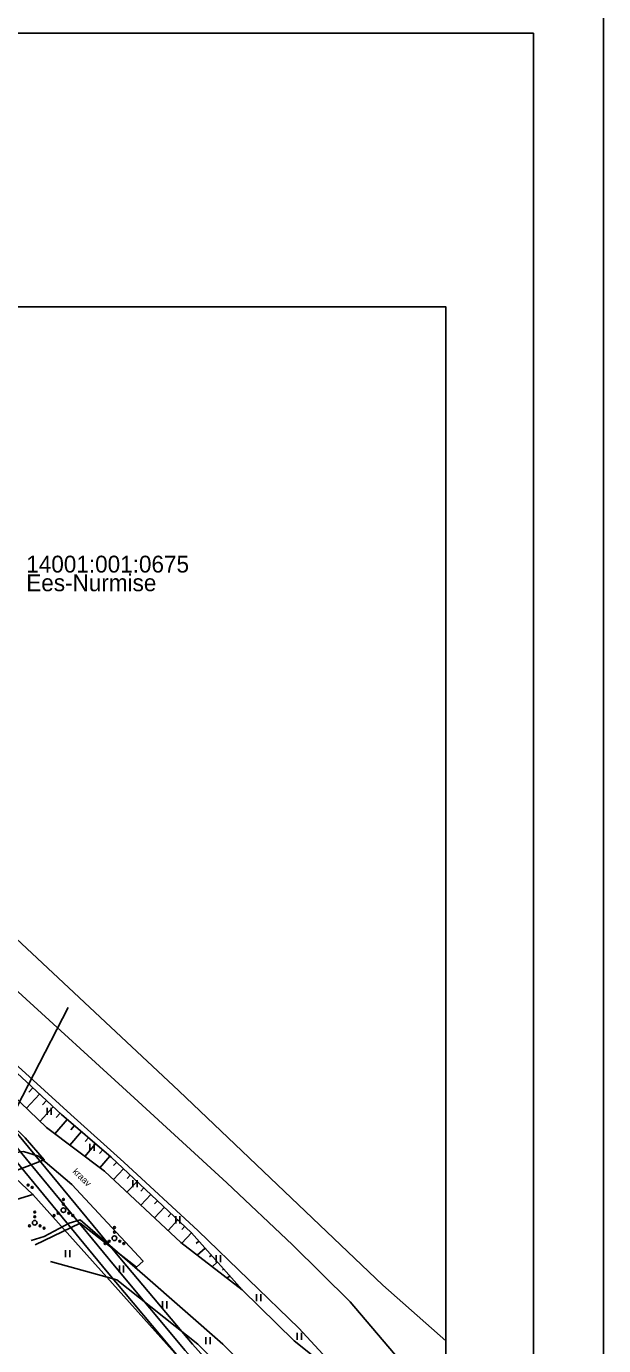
# Model space of a CAD drawing. Extents: x 567864 to 568657, y 6579839 to 6580994.
# Drawn here: x 568587.3 to 568649.1, y 6580268.5 to 6580409.7 of the extents above; entities that cross this region are included whole.
import ezdxf

# ---------------------------------------------------------------- set-up
doc = ezdxf.new("R2010")
doc.units = 0
for name, color, linetype in [('HALJASTUS', 7, 'Continuous'), ('KASUTUSALA', 7, 'Continuous'), ('KPOHULIIN', 7, 'Continuous'), ('PIIR', 7, 'Continuous'), ('PR_SIDE', 7, 'Continuous'), ('RELJEEF', 7, 'Continuous'), ('TEE', 7, 'Continuous'), ('VEEKOGU', 7, 'Continuous'), ('VORMISTUS_4', 7, 'Continuous')]:
    doc.layers.add(name, color=color, linetype=linetype)

msp = doc.modelspace()

# ---------------------------------------------------------------- linework, layer by layer
at = {"layer": 'HALJASTUS'}
for p, q in [((568589.55, 6580293.97), (568589.55, 6580293.21)), ((568590, 6580293.97), (568590, 6580293.21)), ((568594.14, 6580290.1), (568594.14, 6580289.34)), ((568594.59, 6580290.1), (568594.59, 6580289.34)), ((568598.72, 6580286.23), (568598.72, 6580285.47)), ((568599.18, 6580286.23), (568599.18, 6580285.47)), ((568603.31, 6580282.36), (568603.31, 6580281.6)), ((568603.76, 6580282.36), (568603.76, 6580281.6)), ((568591.53, 6580278.73), (568591.53, 6580277.97)), ((568591.99, 6580278.73), (568591.99, 6580277.97)), ((568597.29, 6580277.09), (568597.29, 6580276.33)), ((568597.74, 6580277.09), (568597.74, 6580276.33)), ((568607.63, 6580278.2), (568607.63, 6580277.44)), ((568608.09, 6580278.2), (568608.09, 6580277.44)), ((568601.9, 6580273.26), (568601.9, 6580272.5)), ((568602.36, 6580273.26), (568602.36, 6580272.5)), ((568611.95, 6580274.04), (568611.95, 6580273.28)), ((568612.41, 6580274.04), (568612.41, 6580273.28)), ((568606.52, 6580269.43), (568606.52, 6580268.67)), ((568606.98, 6580269.43), (568606.98, 6580268.67)), ((568616.28, 6580269.89), (568616.28, 6580269.13)), ((568616.74, 6580269.89), (568616.74, 6580269.13))]:
    msp.add_line(p, q, dxfattribs=at)
for points in [[(568588.28, 6580279.3), (568593.1, 6580281.62), (568599.12, 6580276.92), (568599.82, 6580277.57), (568592.22, 6580285.76), (568588.63, 6580288.77), (568587.02, 6580289.28), (568579.99, 6580288.26)], [(568589.92, 6580277.51), (568597.02, 6580275.57), (568605.68, 6580268.67), (568616.86, 6580257.59), (568622.86, 6580249.28), (568628.01, 6580238.44), (568630.13, 6580229.68)]]:
    msp.add_lwpolyline(points, dxfattribs=at)
for centre, radius in [((568587.53, 6580285.7), 0.1), ((568587.97, 6580285.45), 0.1), ((568591.3, 6580284.16), 0.1), ((568588.23, 6580282.81), 0.1), ((568590.74, 6580282.69), 0.1), ((568591.3, 6580283.01), 0.25), ((568591.3, 6580283.66), 0.1), ((568591.87, 6580282.69), 0.1), ((568587.67, 6580281.34), 0.1), ((568588.23, 6580281.66), 0.25), ((568588.23, 6580282.31), 0.1), ((568588.8, 6580281.34), 0.1), ((568590.3, 6580282.44), 0.1), ((568592.3, 6580282.44), 0.1), ((568596.76, 6580281.16), 0.1), ((568589.23, 6580281.09), 0.1), ((568596.76, 6580280.01), 0.25), ((568596.76, 6580280.66), 0.1), ((568595.76, 6580279.43), 0.1), ((568596.2, 6580279.68), 0.1), ((568597.33, 6580279.68), 0.1), ((568597.76, 6580279.43), 0.1)]:
    msp.add_circle(centre, radius, dxfattribs=at)
at = {"layer": 'KASUTUSALA'}
for points in [[(568461.42, 6580407.34), (568494.57, 6580376.2), (568521.29, 6580351.66), (568532.86, 6580340.57), (568578.04, 6580298.89), (568583.69, 6580294.14), (568584.34, 6580293.58), (568584.51, 6580293.44), (568597.53, 6580277.69), (568605.09, 6580268.66), (568620.33, 6580251.61)], [(568603.57, 6580267.35), (568595.99, 6580276.41), (568583.33, 6580291.74), (568581.46, 6580290.83), (568579.89, 6580292.29), (568581.72, 6580293.18), (568576.71, 6580297.39), (568531.49, 6580339.11), (568519.92, 6580350.2), (568493.21, 6580374.74), (568460.06, 6580405.87)]]:
    msp.add_lwpolyline(points, dxfattribs=at)
at = {"layer": 'KPOHULIIN'}
msp.add_lwpolyline([(568591.82, 6580304.68), (568584.43, 6580290.42), (568575.69, 6580287.52)], dxfattribs=at)
at = {"layer": 'PIIR'}
for points in [[(568513.99, 6580379.67), (568517.27, 6580376.68), (568603.64, 6580295.78), (568625.46, 6580274.99), (568632.18, 6580269.03)], [(568632.18, 6580269.03), (568625.46, 6580274.99), (568603.64, 6580295.78), (568517.27, 6580376.68), (568513.99, 6580379.67)], [(568628.53, 6580222.17), (568629.55, 6580235.74), (568618.77, 6580250.35), (568588.05, 6580284.69), (568583.66, 6580288.78), (568508.43, 6580358.86)], [(568508.43, 6580358.86), (568583.66, 6580288.78), (568588.05, 6580284.69), (568508.43, 6580260.29)], [(568508.43, 6580260.29), (568588.05, 6580284.69), (568618.77, 6580250.35), (568629.55, 6580235.74), (568628.53, 6580222.17)]]:
    msp.add_lwpolyline(points, dxfattribs=at)
at = {"layer": 'PR_SIDE'}
msp.add_lwpolyline([(568418.48, 6580444.49), (568438.25, 6580426.85), (568460.74, 6580406.61), (568493.89, 6580375.47), (568520.61, 6580350.93), (568532.18, 6580339.84), (568577.38, 6580298.14), (568583.8, 6580292.74), (568596.76, 6580277.05), (568604.33, 6580268.01), (568619.55, 6580250.98), (568628.57, 6580238.42), (568627.43, 6580222.17)], dxfattribs=at)
at = {"layer": 'RELJEEF'}
for p, q in [((568588.76, 6580295.42), (568587.36, 6580293.91)), ((568588.03, 6580296.1), (568587.61, 6580295.65)), ((568590.22, 6580294.05), (568588.8, 6580292.52)), ((568589.49, 6580294.73), (568589.07, 6580294.28)), ((568591.71, 6580292.71), (568590.39, 6580291.18)), ((568590.95, 6580293.37), (568590.53, 6580292.91)), ((568593.22, 6580291.41), (568591.99, 6580289.97)), ((568592.47, 6580292.06), (568592.08, 6580291.62)), ((568594.74, 6580290.11), (568593.59, 6580288.76)), ((568593.98, 6580290.76), (568593.62, 6580290.34)), ((568595.5, 6580289.45), (568595.16, 6580289.06)), ((568596.26, 6580288.8), (568595.18, 6580287.55)), ((568597.72, 6580287.44), (568596.64, 6580286.29)), ((568596.99, 6580288.12), (568596.67, 6580287.78)), ((568599.18, 6580286.07), (568598.1, 6580284.92)), ((568598.45, 6580286.76), (568598.13, 6580286.41)), ((568600.64, 6580284.7), (568599.57, 6580283.56)), ((568599.91, 6580285.39), (568599.59, 6580285.04)), ((568602.1, 6580283.33), (568601.03, 6580282.2)), ((568601.37, 6580284.02), (568601.05, 6580283.68)), ((568602.83, 6580282.65), (568602.51, 6580282.31)), ((568603.55, 6580281.96), (568602.49, 6580280.83)), ((568604.28, 6580281.28), (568603.97, 6580280.94)), ((568605.79, 6580279.71), (568605.5, 6580279.45)), ((568606.46, 6580278.96), (568605.6, 6580278.21)), ((568607.12, 6580278.21), (568606.91, 6580278.03)), ((568607.78, 6580277.47), (568607.21, 6580276.96)), ((568608.44, 6580276.72), (568608.32, 6580276.6)), ((568609.11, 6580275.97), (568608.82, 6580275.72)), ((568609.77, 6580275.22), (568609.73, 6580275.18)), ((568610.43, 6580274.47), (568610.43, 6580274.47))]:
    msp.add_line(p, q, dxfattribs=at)
for points in [[(568605.01, 6580280.6), (568596.41, 6580288.68), (568591.09, 6580293.25), (568573.56, 6580309.57), (568555.55, 6580325.9), (568539.48, 6580341.11), (568522.9, 6580356.55), (568508.43, 6580369.91)], [(568610.43, 6580274.47), (568605.01, 6580280.6), (568603.96, 6580279.48)]]:
    msp.add_lwpolyline(points, dxfattribs=at)
at = {"layer": 'TEE'}
for points in [[(568632.18, 6580259.41), (568631.27, 6580261.38), (568627.21, 6580267.03), (568621.95, 6580273.22), (568615.8, 6580279.31), (568608.79, 6580285.93), (568598.88, 6580295.04), (568586.08, 6580306.74), (568577.68, 6580314.48), (568563.53, 6580327.85), (568545.36, 6580344.62), (568529.11, 6580359.65), (568512.43, 6580375.18), (568508.43, 6580378.85)], [(568508.43, 6580370.47), (568509.17, 6580369.79), (568522.98, 6580357.19), (568540.01, 6580341.2), (568555.65, 6580326.86), (568574.36, 6580309.39), (568592.09, 6580293.25), (568597.76, 6580288.15), (568605.72, 6580280.8), (568616.48, 6580270.4), (568621.57, 6580264.87), (568624.14, 6580261.44), (568626.74, 6580257.05), (568628.43, 6580254.18), (568629.48, 6580251.71), (568629.92, 6580249.85), (568631.52, 6580242.99), (568632.18, 6580237.44)]]:
    msp.add_lwpolyline(points, dxfattribs=at)
at = {"layer": 'VEEKOGU'}
for points in [[(568581.85, 6580285.88), (568585.24, 6580286.87), (568589.25, 6580288.4), (568587.21, 6580290.75), (568571.08, 6580306.43), (568558.05, 6580318.95), (568554.33, 6580324.09), (568558.12, 6580321.99), (568572.68, 6580308.01), (568589.49, 6580291.86), (568595.68, 6580287.17), (568603.87, 6580279.55), (568610.43, 6580274.47), (568615.96, 6580269.02), (568621.24, 6580264.81)], [(568614.83, 6580262.2), (568608.34, 6580268.67), (568599.99, 6580275.97), (568593.1, 6580281.97), (568591.9, 6580281.62), (568589.25, 6580280.19), (568587.85, 6580279.77)]]:
    msp.add_lwpolyline(points, dxfattribs=at)
at = {"layer": 'VORMISTUS_4'}
for points in [[(568491.55, 6580417.17), (568649.05, 6580417.17), (568649.05, 6580194.42), (568491.55, 6580194.42)], [(568499.05, 6580202.67), (568641.55, 6580202.67), (568641.55, 6580408.92), (568499.05, 6580408.92)], [(568499.05, 6580408.92), (568641.55, 6580408.92), (568641.55, 6580202.67), (568499.05, 6580202.67)], [(568632.18, 6580222.17), (568508.43, 6580222.17), (568508.43, 6580379.67), (568632.18, 6580379.67)]]:
    msp.add_lwpolyline(points, close=True, dxfattribs=at)

# ---------------------------------------------------------------- texts
at = {"layer": 'PIIR'}
for s, p in [('14001:001:0675', (568587.33, 6580351.23)), ('Ees-Nurmise', (568587.33, 6580349.23))]:
    msp.add_text(s, height=1.8, dxfattribs=at).set_placement(p)
at = {"layer": 'VEEKOGU'}
msp.add_text('kraav', height=0.7, rotation=316.1326, dxfattribs=at).set_placement((568592.23, 6580287.06))

doc.saveas('drawing.dxf')
